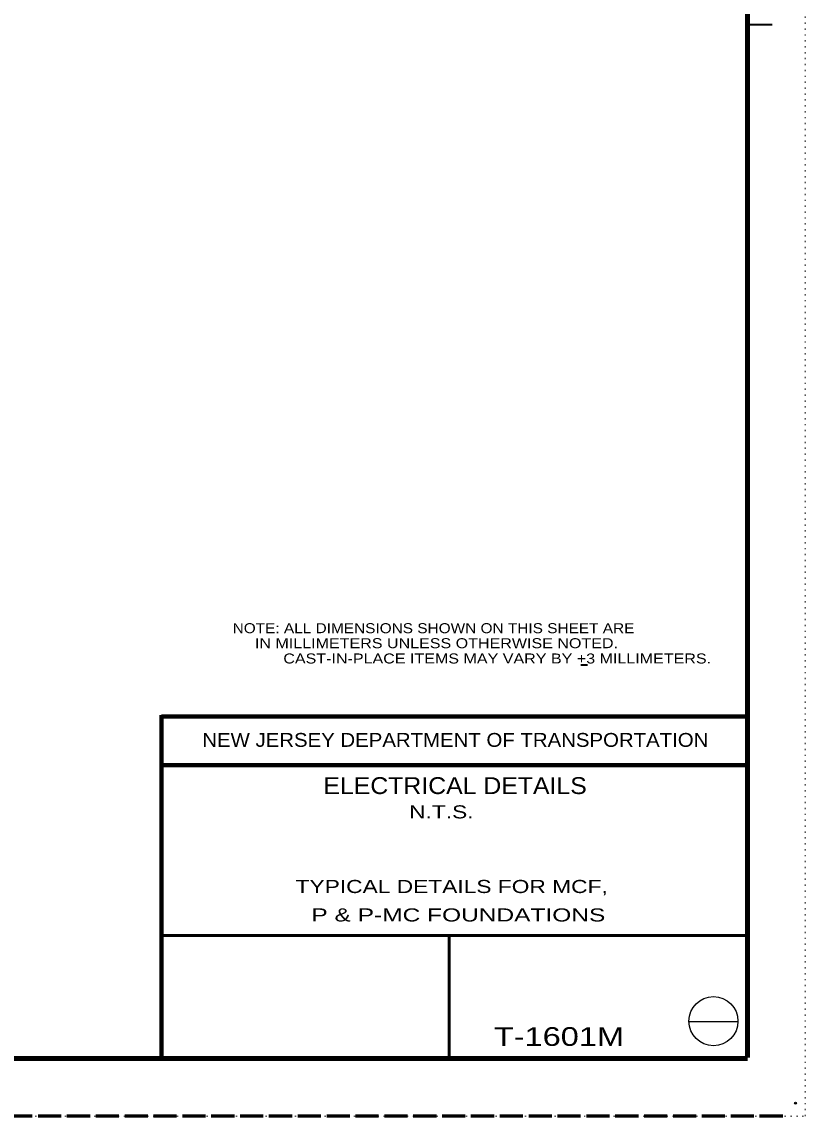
# Model space of a CAD drawing. Extents: x 312583 to 312854, y 144419 to 144597.
# Drawn here: x 312792.4 to 312853.5, y 144418.6 to 144503.8 of the extents above; entities that cross this region are included whole.
import ezdxf
from ezdxf.enums import TextEntityAlignment as Align

# ---------------------------------------------------------------- set-up
doc = ezdxf.new("R2010")
doc.units = 0
doc.header["$LTSCALE"] = 0.3
doc.header["$PDMODE"] = 32
doc.header["$PDSIZE"] = 0.15
doc.linetypes.add('DOTTED', pattern=[1.5, 0.3, -1.2])
doc.linetypes.add('LONG_DASHED', pattern=[7.5, 6, -1.5])
for name, color, linetype, lineweight in [('1', 7, 'Continuous', 25), ('10', 7, 'Continuous', 25), ('2', 7, 'Continuous', 13), ('62', 7, 'DOTTED', 13), ('63', 7, 'LONG_DASHED', 60)]:
    doc.layers.add(name, color=color, linetype=linetype, lineweight=lineweight)

msp = doc.modelspace()

# ---------------------------------------------------------------- linework, layer by layer
at = {"layer": '1', "lineweight": 158}
for p, q in [((312849, 144423.1446), (312849, 144585.0846)), ((312616.5, 144423.0846), (312849, 144423.0846))]:
    msp.add_line(p, q, dxfattribs=at)
at = {"layer": '1', "lineweight": 35}
for p, q in [((312849, 144503.6216), (312850.932, 144503.6216)), ((312836.0248, 144453.7338), (312836.5347, 144453.7338))]:
    msp.add_line(p, q, dxfattribs=at)
at = {"layer": '1', "lineweight": 80}
for p, q in [((312803.31, 144423.1446), (312803.31, 144449.8146)), ((312803.31, 144449.7246), (312849, 144449.7246)), ((312803.31, 144445.9146), (312849, 144445.9146))]:
    msp.add_line(p, q, dxfattribs=at)
at = {"layer": '1', "lineweight": 53}
for p, q in [((312849, 144432.6666), (312803.31, 144432.6666)), ((312825.7547, 144432.6666), (312825.7547, 144423.1446))]:
    msp.add_line(p, q, dxfattribs=at)
at = {"layer": '1'}
msp.add_point((312852.75, 144419.5846), dxfattribs=at)
at = {"layer": '10'}
msp.add_line((312844.4383, 144425.966), (312848.2793, 144425.966), dxfattribs=at)
msp.add_circle((312846.3494, 144425.9805), 1.9159, dxfattribs=at)
at = {"layer": '62'}
msp.add_lwpolyline([(312601.2, 144418.5846), (312853.5, 144418.5846), (312853.5, 144596.7846)], dxfattribs=at)
at = {"layer": '63'}
msp.add_line((312851.75, 144418.5846), (312583.526, 144418.5846), dxfattribs=at)

# ---------------------------------------------------------------- texts
at = {"layer": '1'}
for s, width, p in [('NOTE: ALL DIMENSIONS SHOWN ON THIS SHEET ARE', 1.15, (312808.8669, 144456.209)), ('     IN MILLIMETERS UNLESS OTHERWISE NOTED.', 1.2, (312808.8668, 144455.039)), ('CAST-IN-PLACE ITEMS MAY VARY BY +3 MILLIMETERS.', 1.2, (312812.8177, 144453.8481))]:
    msp.add_text(s, height=0.78, dxfattribs=dict(at, width=width)).set_placement(p)
for s, height, width, p in [('NEW JERSEY DEPARTMENT OF TRANSPORTATION', 1.08, 1.1, (312826.2285, 144447.3546)), ('ELECTRICAL DETAILS', 1.315, 1.1, (312826.2109, 144443.676)), ('T-1601M   ', 1.457, 1.3, (312835.3614, 144424.057))]:
    msp.add_text(s, height=height, dxfattribs=dict(at, width=width)).set_placement(p, align=Align.CENTER)
at = {"layer": '2'}
for s, width, p in [('    N.T.S.  ', 1.3, (312824.6461, 144441.778)), ('        TYPICAL DETAILS FOR MCF,        ', 1.3, (312825.9439, 144435.9652)), ('      P & P-MC FOUNDATIONS       ', 1.4, (312826.7299, 144433.7476))]:
    msp.add_text(s, height=1.02, dxfattribs=dict(at, width=width)).set_placement(p, align=Align.CENTER)

doc.saveas('drawing.dxf')
